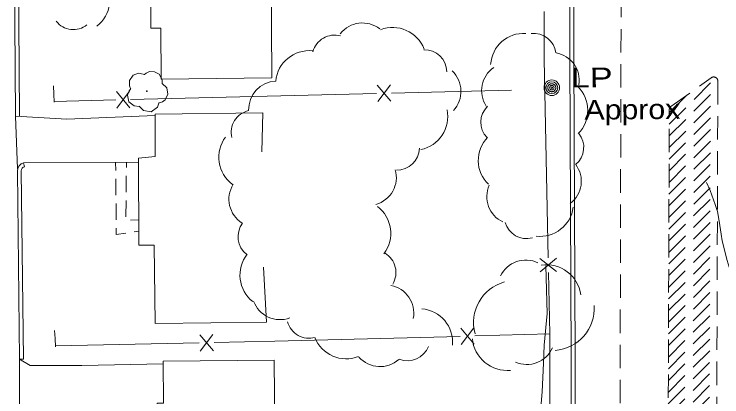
# Model space of a CAD drawing. Extents: x 2361284 to 2366480, y 6976556 to 6985346.
# Drawn here: x 2361533.2 to 2361705.6, y 6977914.8 to 6978008.1 of the extents above; entities that cross this region are included whole.
import ezdxf

# ---------------------------------------------------------------- set-up
doc = ezdxf.new("R2010")
doc.units = 0
doc.header["$LTSCALE"] = 1.9
doc.linetypes.add('MEDIUM_DASHED', pattern=[4.5, 3, -1.5])
for name, color, linetype, lineweight in [('13', 7, 'Continuous', 13), ('16', 7, 'Continuous', 13), ('19', 7, 'Continuous', 13), ('3', 7, 'Continuous', 13), ('4', 7, 'Continuous', 13), ('5', 7, 'Continuous', 13), ('7', 7, 'Continuous', 13), ('9', 7, 'Continuous', 13)]:
    doc.layers.add(name, color=color, linetype=linetype, lineweight=lineweight)

msp = doc.modelspace()

# ---------------------------------------------------------------- linework, layer by layer
at = {"layer": '13'}
for points in [[(2361701.911, 6977967.046), (2361702.78, 6977965.056), (2361704.053, 6977961.667), (2361704.559, 6977959.931), (2361705.025, 6977957.582), (2361705.49, 6977954.424), (2361705.766, 6977952.852), (2361706.912, 6977948.023), (2361707.44, 6977946.429), (2361707.896, 6977945.405), (2361708.976, 6977943.413), (2361709.221, 6977943.167), (2361709.949, 6977942.927), (2361710.232, 6977943.018), (2361710.31, 6977943.135), (2361710.751, 6977944.62), (2361711.277, 6977947.665), (2361711.478, 6977949.667), (2361711.559, 6977952.738)], [(2361596.708, 6977906.823), (2361598.168, 6977907.907), (2361602.344, 6977909.457), (2361607.443, 6977910.625), (2361612.271, 6977910.871), (2361617.206, 6977910.348), (2361621.283, 6977908.617), (2361625.157, 6977907.174), (2361628.355, 6977905.324), (2361631.777, 6977902.967), (2361635.814, 6977900.185), (2361637.696, 6977899.387), (2361641.82, 6977899.562), (2361647.671, 6977902.638), (2361649.467, 6977903.115), (2361655.968, 6977905.117), (2361659.018, 6977906.196), (2361661.198, 6977908.337), (2361661.855, 6977915.972), (2361662.148, 6977922.986), (2361662.316, 6977927.408), (2361663.113, 6977935.086), (2361662.733, 6977946.723)]]:
    msp.add_lwpolyline(points, dxfattribs=at)
at = {"layer": '16'}
for points in [[(2361561.576, 6977989.874), (2361561.596, 6977989.885), (2361561.516, 6977989.954), (2361561.28, 6977990.582), (2361561.317, 6977991.862), (2361562.205, 6977993.161), (2361563.511, 6977993.643), (2361564.632, 6977993.454), (2361564.864, 6977993.326), (2361564.934, 6977993.326), (2361564.983, 6977993.367), (2361565.331, 6977993.66), (2361566.196, 6977994.109), (2361567.407, 6977994.04), (2361568.523, 6977993.451), (2361569.256, 6977992.028), (2361569.264, 6977991.168)], [(2361569.254, 6977991.187), (2361570.394, 6977990.128), (2361570.68, 6977988.541), (2361569.972, 6977987.214), (2361569.317, 6977986.668), (2361568.649, 6977986.451), (2361568.499, 6977986.44), (2361568.48, 6977986.33), (2361568.159, 6977985.427), (2361566.62, 6977984.262), (2361564.727, 6977984.544), (2361563.828, 6977985.486), (2361563.757, 6977985.615), (2361563.637, 6977985.594), (2361562.426, 6977985.712), (2361561.156, 6977986.71), (2361560.811, 6977988.347), (2361561.181, 6977989.371), (2361561.507, 6977989.814), (2361561.576, 6977989.864)]]:
    msp.add_lwpolyline(points, dxfattribs=at)
msp.add_circle((2361565.542, 6977989.302), 0.1, dxfattribs=at)
for centre, radius, start, end in [((2361548.48, 6978011.461), 7.988, 307.82061, 37.82061), ((2361547.641, 6978009.618), 5.322, 218.11106, 308.11106), ((2361618.057, 6977999.056), 6.861, 52.08077, 142.08077), ((2361625.403, 6977996.596), 8.229, 20.95711, 110.95711), ((2361611.266, 6977997.475), 5.482, 74.84727, 164.84727), ((2361657.388, 6977995.282), 8.1, 86.2843, 176.2843), ((2361659.831, 6977997.974), 5.396, 7.05599, 97.05599), ((2361605.111, 6977990.938), 8.229, 84.41015, 174.41015), ((2361633.157, 6977993.904), 5.482, 1.47039, 91.47039), ((2361664.143, 6977991.943), 6.753, 350.69571, 80.69571), ((2361653.845, 6977989.448), 6.753, 123.99388, 213.99388), ((2361635.205, 6977989.25), 6.861, 316.90417, 46.90417), ((2361597.196, 6977984.865), 6.861, 92.13495, 182.13495), ((2361664.871, 6977984.641), 8.1, 315.32821, 45.32821), ((2361630.613, 6977983.11), 8.229, 281.57172, 11.57172), ((2361652.311, 6977981.711), 5.396, 133.86949, 223.86949), ((2361591.564, 6977979.218), 5.482, 103.08528, 193.08528), ((2361591.304, 6977973.173), 8.229, 143.38473, 233.38473), ((2361654.39, 6977972.418), 8.1, 136.04579, 226.04579), ((2361666.603, 6977975.588), 5.396, 309.37391, 39.37391), ((2361626.451, 6977975.508), 5.482, 268.7326, 358.7326), ((2361664.648, 6977967.329), 6.753, 306.96157, 36.96157), ((2361619.477, 6977968.279), 6.861, 285.88179, 15.88179), ((2361592.392, 6977962.972), 6.861, 148.01823, 238.01823), ((2361655.122, 6977963.553), 6.753, 155.36148, 245.36148), ((2361616.732, 6977954.651), 8.229, 322.87204, 52.87204), ((2361661.382, 6977962.008), 8.1, 262.94953, 352.94953), ((2361593.215, 6977953.815), 5.482, 142.5567, 232.5567), ((2361658.036, 6977958.756), 5.396, 195.42776, 285.42776), ((2361596.45, 6977944.439), 8.229, 141.6346, 231.6346), ((2361620.746, 6977945.122), 5.482, 328.74116, 58.74116), ((2361657.86, 6977941.292), 6.83, 64.29372, 154.29372), ((2361662.842, 6977938.43), 8.546, 8.15884, 98.15884), ((2361623.714, 6977935.213), 6.861, 349.14392, 79.14392), ((2361655.389, 6977932.903), 10.25, 105.45752, 195.45752), ((2361597.996, 6977940.461), 6.861, 199.92979, 289.92979), ((2361664.317, 6977936.347), 10.25, 273.80952, 3.80952), ((2361631.814, 6977928.05), 8.229, 355.15726, 85.15726), ((2361605.073, 6977934.535), 5.482, 195.45071, 285.45071), ((2361614.113, 6977932.268), 8.229, 201.4702, 291.4702), ((2361653.354, 6977929.752), 8.546, 185.39728, 275.39728), ((2361629.054, 6977929.086), 5.482, 248.43464, 338.43464), ((2361658.15, 6977929.508), 6.83, 246.03212, 336.03212), ((2361622.349, 6977929.022), 6.861, 221.62771, 311.62771)]:
    msp.add_arc(centre, radius, start, end, dxfattribs=at)
at = {"layer": '19'}
for p, q in [((2361557.928, 6977971.928), (2361557.947, 6977969.928)), ((2361560.53, 6977970.662), (2361560.538, 6977971.943)), ((2361557.966, 6977967.928), (2361557.994, 6977963.929)), ((2361560.478, 6977964.663), (2361560.509, 6977968.662)), ((2361560.435, 6977958.661), (2361560.467, 6977962.661)), ((2361558.013, 6977961.928), (2361558.041, 6977957.928)), ((2361563.571, 6977957.931), (2361561.571, 6977957.852)), ((2361562.409, 6977954.97), (2361563.587, 6977955.151))]:
    msp.add_line(p, q, dxfattribs=at)
msp.add_lwpolyline([(2361558.05, 6977955.928), (2361558.066, 6977954.318), (2361560.433, 6977954.671)], dxfattribs=at)
at = {"layer": '3', "linetype": 'MEDIUM_DASHED'}
for p, q in [((2361681.599, 6978218.192), (2361680.648, 6977831.452)), ((2361692.824, 6977981.224), (2361704.205, 6977992.605)), ((2361693.252, 6977985.523), (2361703.078, 6977992.578)), ((2361704.662, 6977991.764), (2361704.235, 6977859.767)), ((2361692.814, 6977978.386), (2361704.657, 6977990.229)), ((2361692.833, 6977984.061), (2361696.949, 6977988.177)), ((2361692.805, 6977975.548), (2361704.648, 6977987.391)), ((2361692.409, 6977854.696), (2361692.835, 6977984.713)), ((2361692.796, 6977972.71), (2361704.639, 6977984.553)), ((2361692.786, 6977969.873), (2361704.629, 6977981.716)), ((2361692.777, 6977967.035), (2361704.62, 6977978.878)), ((2361692.768, 6977964.197), (2361704.611, 6977976.041)), ((2361692.758, 6977961.36), (2361704.602, 6977973.203)), ((2361692.749, 6977958.522), (2361704.593, 6977970.365)), ((2361692.74, 6977955.684), (2361704.584, 6977967.528)), ((2361692.731, 6977952.846), (2361704.574, 6977964.69)), ((2361692.721, 6977950.009), (2361704.565, 6977961.853)), ((2361692.712, 6977947.171), (2361704.556, 6977959.015)), ((2361692.703, 6977944.333), (2361704.547, 6977956.177)), ((2361692.693, 6977941.496), (2361704.538, 6977953.34)), ((2361692.684, 6977938.658), (2361704.529, 6977950.502)), ((2361692.675, 6977935.82), (2361704.519, 6977947.665)), ((2361692.666, 6977932.982), (2361704.51, 6977944.827)), ((2361692.656, 6977930.145), (2361704.501, 6977941.989)), ((2361692.647, 6977927.307), (2361704.492, 6977939.152)), ((2361692.638, 6977924.469), (2361704.483, 6977936.314)), ((2361692.628, 6977921.631), (2361704.473, 6977933.477)), ((2361692.619, 6977918.794), (2361704.464, 6977930.639)), ((2361692.61, 6977915.956), (2361704.455, 6977927.801)), ((2361692.6, 6977913.118), (2361704.446, 6977924.964)), ((2361692.591, 6977910.281), (2361704.437, 6977922.126)), ((2361692.582, 6977907.443), (2361704.428, 6977919.289)), ((2361692.573, 6977904.605), (2361704.418, 6977916.451))]:
    msp.add_line(p, q, dxfattribs=at)
at = {"layer": '3'}
for p, q in [((2361534.041, 6977970.381), (2361533.559, 6977983.207)), ((2361535.477, 6977971.814), (2361563.507, 6977971.961)), ((2361535.507, 6977971.825), (2361535.726, 6977970.887)), ((2361535.473, 6977923.942), (2361534.513, 6977923.933)), ((2361534.513, 6977923.933), (2361534.535, 6977910.031))]:
    msp.add_line(p, q, dxfattribs=at)
for points in [[(2361668.929, 6977831.572), (2361668.929, 6977831.546), (2361668.856, 6977863.456), (2361668.929, 6977924.071), (2361668.628, 6977997.801), (2361668.439, 6978089.285), (2361668.419, 6978223.902)], [(2361669.889, 6977831.545), (2361669.889, 6977831.545), (2361669.816, 6977863.456), (2361669.889, 6977924.07), (2361669.588, 6977997.801), (2361669.399, 6978089.284), (2361669.379, 6978223.901)], [(2361533.193, 6978029.156), (2361533.192, 6978029.155), (2361533.559, 6977983.207)], [(2361534.15, 6978029.08), (2361534.152, 6978029.164), (2361534.519, 6977983.216)], [(2361533.559, 6977983.207), (2361546.057, 6977982.445), (2361567.589, 6977983.37)], [(2361533.978, 6977969.83), (2361533.976, 6977969.83), (2361534.513, 6977923.933)], [(2361534.937, 6977969.859), (2361534.936, 6977969.839), (2361535.473, 6977923.942)], [(2361534.513, 6977923.933), (2361537.087, 6977922.417), (2361549.678, 6977922.387), (2361569.515, 6977922.816)]]:
    msp.add_lwpolyline(points, dxfattribs=at)
at = {"layer": '3', "linetype": 'MEDIUM_DASHED'}
for centre, start, end in [((2361703.662, 6977991.766), 359.85891, 125.67865), ((2361693.835, 6977984.711), 125.67869, 179.85914)]:
    msp.add_arc(centre, 1, start, end, dxfattribs=at)
at = {"layer": '3'}
for radius, start, end in [(1.989, 103.32805, 181.70243), (1.029, 103.32807, 181.70244)]:
    msp.add_arc((2361535.966, 6977969.889), radius, start, end, dxfattribs=at)
at = {"layer": '4'}
for radius in [1.9, 1.442, 0.539, 0.192]:
    msp.add_circle((2361664.21, 6977990.14), radius, dxfattribs=at)
for start, end in [(174.71552, 185.96556), (163.46611, 174.71615), (185.96287, 197.21291), (152.21535, 163.46538), (197.21479, 208.46483), (140.96646, 152.21649), (129.71376, 140.96379), (118.46406, 129.71409), (107.21593, 118.46597), (95.96582, 107.21585), (84.71553, 95.96557), (73.46552, 84.71555), (62.21535, 73.46538), (50.96397, 62.214), (39.71588, 50.96591), (28.46656, 39.7166), (17.21479, 28.46483), (332.21419, 343.46422), (5.96345, 17.21348), (343.46611, 354.71615), (354.71553, 5.96557), (208.46822, 219.71826), (219.71376, 230.96379), (230.96397, 242.214), (242.21812, 253.46815), (253.46258, 264.71261), (264.71553, 275.96557), (275.96582, 287.21585), (287.21593, 298.46597), (298.46406, 309.71409), (309.71589, 320.96592), (320.96646, 332.21649)]:
    msp.add_arc((2361664.21, 6977990.14), 0.973, start, end, dxfattribs=at)
at = {"layer": '5'}
for points in [[(2361542.955, 6977986.588), (2361542.861, 6977988.576), (2361542.766, 6977990.574)], [(2361543.302, 6977926.988), (2361543.156, 6977928.973), (2361543.009, 6977930.967)]]:
    msp.add_lwpolyline(points, dxfattribs=at)
at = {"layer": '7'}
for points in [[(2361596.023, 6977992.522), (2361569.015, 6977992.255), (2361568.896, 6978004.683), (2361566.536, 6978004.661), (2361566.388, 6978020.301), (2361568.678, 6978020.323), (2361568.551, 6978033.613), (2361569.411, 6978033.621), (2361569.313, 6978043.93), (2361594.802, 6978044.173), (2361594.898, 6978034.103), (2361597.488, 6978034.128), (2361597.643, 6978017.808), (2361595.783, 6978017.791)], [(2361596.557, 6977923.753), (2361597.016, 6977872.374), (2361570.107, 6977872.138), (2361569.932, 6977891.587), (2361568.212, 6977891.571), (2361568.006, 6977913.24), (2361569.606, 6977913.255), (2361569.508, 6977923.496)]]:
    msp.add_lwpolyline(points, close=True, dxfattribs=at)
msp.add_lwpolyline([(2361593.962, 6977946.409), (2361594.719, 6977932.986), (2361567.551, 6977932.637), (2361567.329, 6977951.796), (2361563.599, 6977951.781), (2361563.497, 6977973.001), (2361567.594, 6977973.37), (2361567.586, 6977983.69), (2361593.784, 6977983.999), (2361593.584, 6977974.507)], dxfattribs=at)
at = {"layer": '9'}
for p, q in [((2361624.98, 6977986.827), (2361621.682, 6977990.746)), ((2361621.78, 6977986.746), (2361624.882, 6977990.826)), ((2361561.401, 6977985.271), (2361558.104, 6977989.191)), ((2361558.202, 6977985.191), (2361561.303, 6977989.272)), ((2361561.552, 6977987.234), (2361621.532, 6977988.704)), ((2361625.131, 6977988.788), (2361654.375, 6977989.517)), ((2361542.955, 6977986.787), (2361557.954, 6977987.15)), ((2361665.377, 6977945.348), (2361661.316, 6977948.47)), ((2361665.316, 6977948.548), (2361661.376, 6977945.27)), ((2361663.721, 6977930.112), (2361663.408, 6977945.109)), ((2361642.016, 6977931.515), (2361645.325, 6977927.597)), ((2361645.217, 6977931.596), (2361642.124, 6977927.516)), ((2361578.449, 6977929.921), (2361581.736, 6977925.992)), ((2361581.648, 6977929.991), (2361578.537, 6977925.922)), ((2361578.297, 6977927.959), (2361543.302, 6977927.187))]:
    msp.add_line(p, q, dxfattribs=at)
for points in [[(2361663.334, 6977948.709), (2361662.345, 6977996.982), (2361662.353, 6978008.703)], [(2361641.875, 6977929.534), (2361596.753, 6977928.355), (2361581.897, 6977928.034)], [(2361663.667, 6977888.398), (2361663.751, 6977930.112), (2361645.475, 6977929.628)]]:
    msp.add_lwpolyline(points, dxfattribs=at)

# ---------------------------------------------------------------- texts
at = {"layer": '4'}
for s, width, p in [('  LP', 1.3, (2361664.21, 6977990.14)), ('Approx', 1.15, (2361672.176, 6977982.334))]:
    msp.add_text(s, height=4.799, rotation=0.545, dxfattribs=dict(at, width=width)).set_placement(p)

doc.saveas('drawing.dxf')
